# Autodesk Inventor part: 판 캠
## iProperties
Created: 2012-05
Part Number: 판 캠
Document SubType Name: 모델링
Designer: SeoGD™
변환 표준: STEP AP214IS
파일 이름: C:\Users\SeoGD\Desktop\?쒗뿕\??stp
전처리기: Build: 253, Release: 2010 SP1 - Date: Wed 07/29/2009
전송 단위: 밀리미터
불확실성: 0.01
Author: SeoGD™
